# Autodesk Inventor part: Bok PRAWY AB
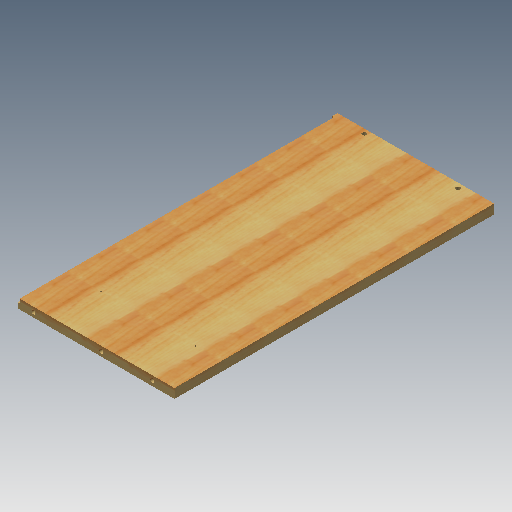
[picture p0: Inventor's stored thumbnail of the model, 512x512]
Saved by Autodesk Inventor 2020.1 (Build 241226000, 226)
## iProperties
Created: 2005-10
Part Number: Bok PRAWY AB
Document SubType Name: Modeling
Designer: F.Stasiak
Density: 1 g/cm^3
Material: Ogólny
Appearance: Drewno (sosna)
Manager: www.cadconsulting.pl
Company: Fabian Stasiak CAD Consulting
Author: F.Stasiak
Subject: Zbiór ćwiczeń. Autodesk Inventor 2020. Kurs podstawowy
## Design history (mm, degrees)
derived "Bok LEWY AB.ipt"
  sketch "Szkic1"
    geometry: L1 (150, 9)-(-150, 9) reference; L2 (-150, 9)-(-150, -9) reference; L3 (-150, -9)-(150, -9) reference; L4 (150, -9)-(150, 9) reference; L5 (0, 9)-(0, -9) reference; L6 (150, 1)-(146.5, 1) reference; L7 (146.5, 1)-(146.5, 9) reference; L8 (-150, 0)-(150, 0) reference; 5 further points
node "Bryła1"
node "Korpusy bryłowe"
node "Korpusy powierzchniowe"
tag "Bryła wyprowadzona2"
feature "Bryła1::Bok LEWY AB.ipt" dims "d0" = 10
